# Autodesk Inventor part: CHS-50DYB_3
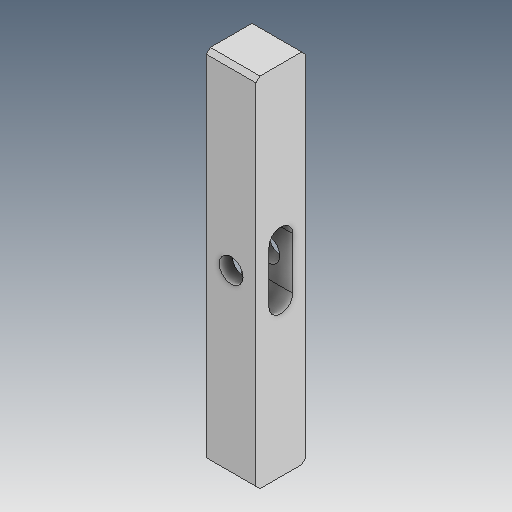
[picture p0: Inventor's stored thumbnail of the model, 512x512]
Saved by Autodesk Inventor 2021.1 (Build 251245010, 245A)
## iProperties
Created: 2019-04
Part Number: CHS-50DYB_3
Material: Ogólny
Document SubType Name: Modeling
Designer: user
Density: 1 g/cm^3
Appearance: Domyślna
Author: user
Revision Number: ÈÎºÎ
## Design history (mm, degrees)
feature "ÊäÈë1"
node "Bryła1"
